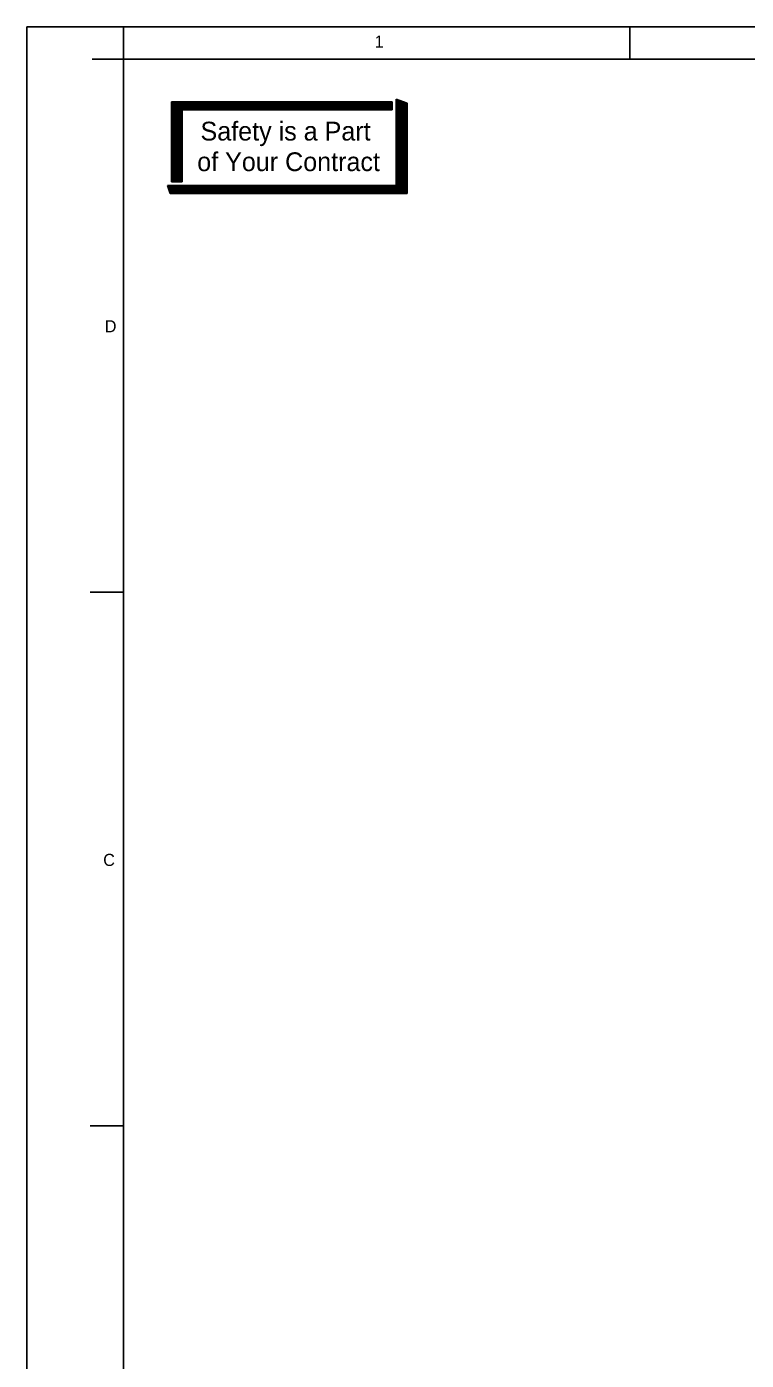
# Model space of a CAD drawing. Extents: x 22422.9 to 22498.9, y 22369.6 to 22415.
# Drawn here: x 22440.26 to 22455.11, y 22387.46 to 22414.97 of the extents above; entities that cross this region are included whole.
import ezdxf

# ---------------------------------------------------------------- set-up
doc = ezdxf.new("R2010")
doc.units = 0
for name, color, linetype in [('Level 1', 7, 'Continuous'), ('Level 10', 7, 'Continuous'), ('Level 9', 7, 'Continuous')]:
    doc.layers.add(name, color=color, linetype=linetype)

msp = doc.modelspace()

# ---------------------------------------------------------------- linework, layer by layer
at = {"layer": 'Level 1'}
msp.add_lwpolyline([(22440.26, 22414.965), (22498.927, 22414.965), (22498.927, 22369.621), (22440.26, 22369.621)], close=True, dxfattribs=at)
at = {"layer": 'Level 10'}
for p, q in [((22442.26, 22414.293), (22442.26, 22414.965)), ((22452.703, 22414.293), (22452.703, 22414.965)), ((22441.609, 22414.293), (22442.253, 22414.293)), ((22443.246, 22413.418), (22447.802, 22413.418)), ((22443.246, 22413.418), (22443.246, 22411.764)), ((22443.246, 22413.397), (22447.802, 22413.397)), ((22443.246, 22413.377), (22447.802, 22413.377)), ((22443.246, 22413.356), (22447.802, 22413.356)), ((22443.246, 22413.334), (22447.802, 22413.334)), ((22443.246, 22413.314), (22447.802, 22413.314)), ((22443.246, 22413.293), (22447.802, 22413.293)), ((22443.246, 22413.273), (22447.802, 22413.273)), ((22443.267, 22413.418), (22443.267, 22411.764)), ((22443.287, 22413.418), (22443.287, 22411.764)), ((22443.308, 22413.418), (22443.308, 22411.764)), ((22443.328, 22413.418), (22443.328, 22411.764)), ((22443.35, 22413.418), (22443.35, 22411.764)), ((22443.371, 22413.418), (22443.371, 22411.764)), ((22443.391, 22413.418), (22443.391, 22411.764)), ((22443.412, 22413.418), (22443.412, 22411.764)), ((22443.434, 22413.418), (22443.434, 22411.764)), ((22443.454, 22413.418), (22443.454, 22411.764)), ((22443.468, 22413.252), (22447.802, 22413.252)), ((22443.468, 22413.252), (22443.468, 22411.764)), ((22447.802, 22413.418), (22447.802, 22413.252)), ((22447.886, 22413.468), (22447.886, 22411.689)), ((22447.886, 22413.468), (22448.108, 22413.385)), ((22447.9, 22413.462), (22447.9, 22411.522)), ((22447.92, 22413.454), (22447.92, 22411.522)), ((22447.942, 22413.446), (22447.942, 22411.522)), ((22447.963, 22413.438), (22447.963, 22411.522)), ((22447.983, 22413.432), (22447.983, 22411.522)), ((22448.004, 22413.424), (22448.004, 22411.522)), ((22448.024, 22413.416), (22448.024, 22411.522)), ((22448.046, 22413.408), (22448.046, 22411.522)), ((22448.067, 22413.401), (22448.067, 22411.522)), ((22448.087, 22413.385), (22448.087, 22411.522)), ((22448.108, 22413.385), (22448.108, 22411.522)), ((22443.162, 22411.689), (22447.886, 22411.689)), ((22443.162, 22411.689), (22443.223, 22411.522)), ((22443.17, 22411.668), (22447.9, 22411.668)), ((22443.176, 22411.648), (22447.9, 22411.648)), ((22443.184, 22411.626), (22447.9, 22411.626)), ((22443.192, 22411.605), (22447.9, 22411.605)), ((22443.2, 22411.585), (22447.9, 22411.585)), ((22443.246, 22411.764), (22443.468, 22411.764)), ((22443.208, 22411.564), (22447.9, 22411.564)), ((22443.215, 22411.544), (22447.9, 22411.544)), ((22443.223, 22411.522), (22448.108, 22411.522)), ((22441.567, 22403.301), (22442.239, 22403.301)), ((22441.567, 22392.293), (22442.239, 22392.293))]:
    msp.add_line(p, q, dxfattribs=at)
at = {"layer": 'Level 9'}
for p, q in [((22442.26, 22370.293), (22442.26, 22414.293)), ((22442.26, 22414.293), (22494.591, 22414.293))]:
    msp.add_line(p, q, dxfattribs=at)

# ---------------------------------------------------------------- texts
at = {"layer": 'Level 1'}
for s, p in [('1', (22447.439, 22414.533)), ('D', (22441.871, 22408.661)), ('C', (22441.839, 22397.653))]:
    msp.add_text(s, height=0.25, dxfattribs=at).set_placement(p)
at = {"layer": 'Level 10'}
for s, p in [('Safety is a Part', (22443.846, 22412.617)), ('of Your Contract', (22443.778, 22411.986))]:
    msp.add_text(s, height=0.38717, dxfattribs=at).set_placement(p)

doc.saveas('drawing.dxf')
